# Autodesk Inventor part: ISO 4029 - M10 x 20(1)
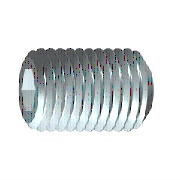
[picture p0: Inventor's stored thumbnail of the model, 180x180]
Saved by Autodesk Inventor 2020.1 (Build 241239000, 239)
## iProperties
Created: 2019-01
Part Number: ISO 4029 - M10 x 20(1)
Material: Edelstahl, 440C
Description: Innensechskant-Gewindestift mit Ringschneide
Document SubType Name: Modeling
Standard: ISO 4029
Designer: lutzd
Standard Revision: Third edition 2003-12-01
Standards Organization: ISO
Language: de-DE
Size Designation: M10 x 20
Categories: <MemberInstance><Categories><Category DisplayName="Verbindungselemente" InternalName="e4da775c-781d-43d5-af7c-5136215cf5a6" Mnemonic="FSTN"><Category DisplayNam
Mass: 10.4089 g
Surface Area: 8.46757 cm^2
Volume: 1.34309 cm^3
Density: 7.75 g/cm^3
Appearance: Halbpoliert
IsCustomPart: 0
Author: lutzd
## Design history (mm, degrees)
sketch "Skizze1"
  geometry: L1 (1.732, 0)-(12.333, 0); L2 (20, 2.887)-(20, 5); L3 (20, 5)-(0, 5); L4 (20, 2.887)-(14, 2.887); L5 (14, 2.887)-(12.333, 0); L6 (0, 3)-(1.732, 0); L7 (0, -1)-(0, 6) reference; L8 (0, 3)-(0, 5); 1 further point
  constraints: 14 end point, 2 parallel, 2 perpendicular, 2 point on line, 1 horizontal
  dimensions: "d0" = 6 distance of L2.start L4.end (= INTI); "d1" = 60 deg angle of L5 L1; "d2" = 10 diameter of L3 L1 (= NND); "d3" = 5.7735 diameter of L4 L1 (= 1.1547 x SW); "d4" = 20 distance from line of L2 L6.start (= NLG); "d5" = 60 deg angle of L1 L6 (= 0.5 x ANG); "d7" = 6 diameter of L6.start L1 (= SPD)
revolve "Körper" sketch "Skizze1" stored, may be unused: angle "d6" = 90 deg
sketch "Skizze2"
  geometry: L1 (2.887, 0)-(1.443, -2.5); L2 (1.443, -2.5)-(-1.443, -2.5); L3 (-1.443, -2.5)-(-2.887, 0); L4 (-2.887, 0)-(-1.443, 2.5); L5 (-1.443, 2.5)-(1.443, 2.5); L6 (1.443, 2.5)-(2.887, 0); C1 r 5 at (0, 0) reference; A1 r 2.887 centre (0, 0) between (2.887, 0) and (1.443, -2.5) reference; 1 further point
  constraints: 12 end point, 2 point on circle, 1 coincident, 1 horizontal, 11 other
extrude "Loch" join sketch "Skizze2" distance "d8" = 6 (= INTI); taper "d9" = 0 deg
workaxis "Work Axis1"
workplane "Work Plane1"
body "Solid1"
chamfer "Fase1" distance "d10" = 2 (= -0.5 x SPD + 0.5 x NND); stored, may be unused: angle "d11" = 45 deg (= FAWI), second distance "d33" = 2 (= -0.5 x SPD + 0.5 x NND)
feature "Gewinde" dims "d14" = 20 (= NLG), "d15" = 0
chamfer "Fase2" distance "d12" = 0.92018 (= -0.5 x GD1 + 0.5 x NND); stored, may be unused: angle "d13" = 45 deg (= FAWI), second distance "d34" = 0.92018 (= -0.5 x GD1 + 0.5 x NND)
other parameters: "NND" = 10 [user parameter; used in 5 equation terms], "NLG" = 20 [user parameter; used in 2 equation terms], "INTI" = 6 [user parameter; used in 2 equation terms], "FAWI" = 45 deg [user parameter; used in 2 equation terms], "SW" = 5 [user parameter; used in 2 equation terms], "GD1" = 8.15965 (= THREADDIA - 1.2269 x PTC) [user parameter; used in 2 equation terms], "ANG" = 120 deg [user parameter; used in 1 equation term], "FAWI1" = 45 deg [user parameter], "SPD" = 6 [user parameter; used in 3 equation terms], "d16" = 0, "d35" = 0, "d37" = 0, "GUL" = 0.92018 (= 0.61345 x PTC) [user parameter], "TPU" = 6.66667 (computed from PTC) [user parameter], "TOA" = 30 deg [user parameter], "PTC" = 1.5 [user parameter; used in 4 equation terms], "GAL" = 0.92018 (= 0.61345 x PTC) [user parameter], "E0" = 5.775 (= 1.155 x SW) [user parameter]
